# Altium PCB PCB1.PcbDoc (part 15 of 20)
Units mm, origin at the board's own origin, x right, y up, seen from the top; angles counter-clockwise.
Board outline 294.51 x 138.18 mm, 12 copper layers (Top Layer 1 _Signal, L2_GND, L3_Signals, L4_GND, L5_POWER, L6_Signals, L7_GND, L8_Signals, L9_GND, L10_POWER, L11_GND, Bottom Layer_Signals), stack 1.788 mm thick; 1254 components, 836 nets, 5699 pads, 2073 vias.
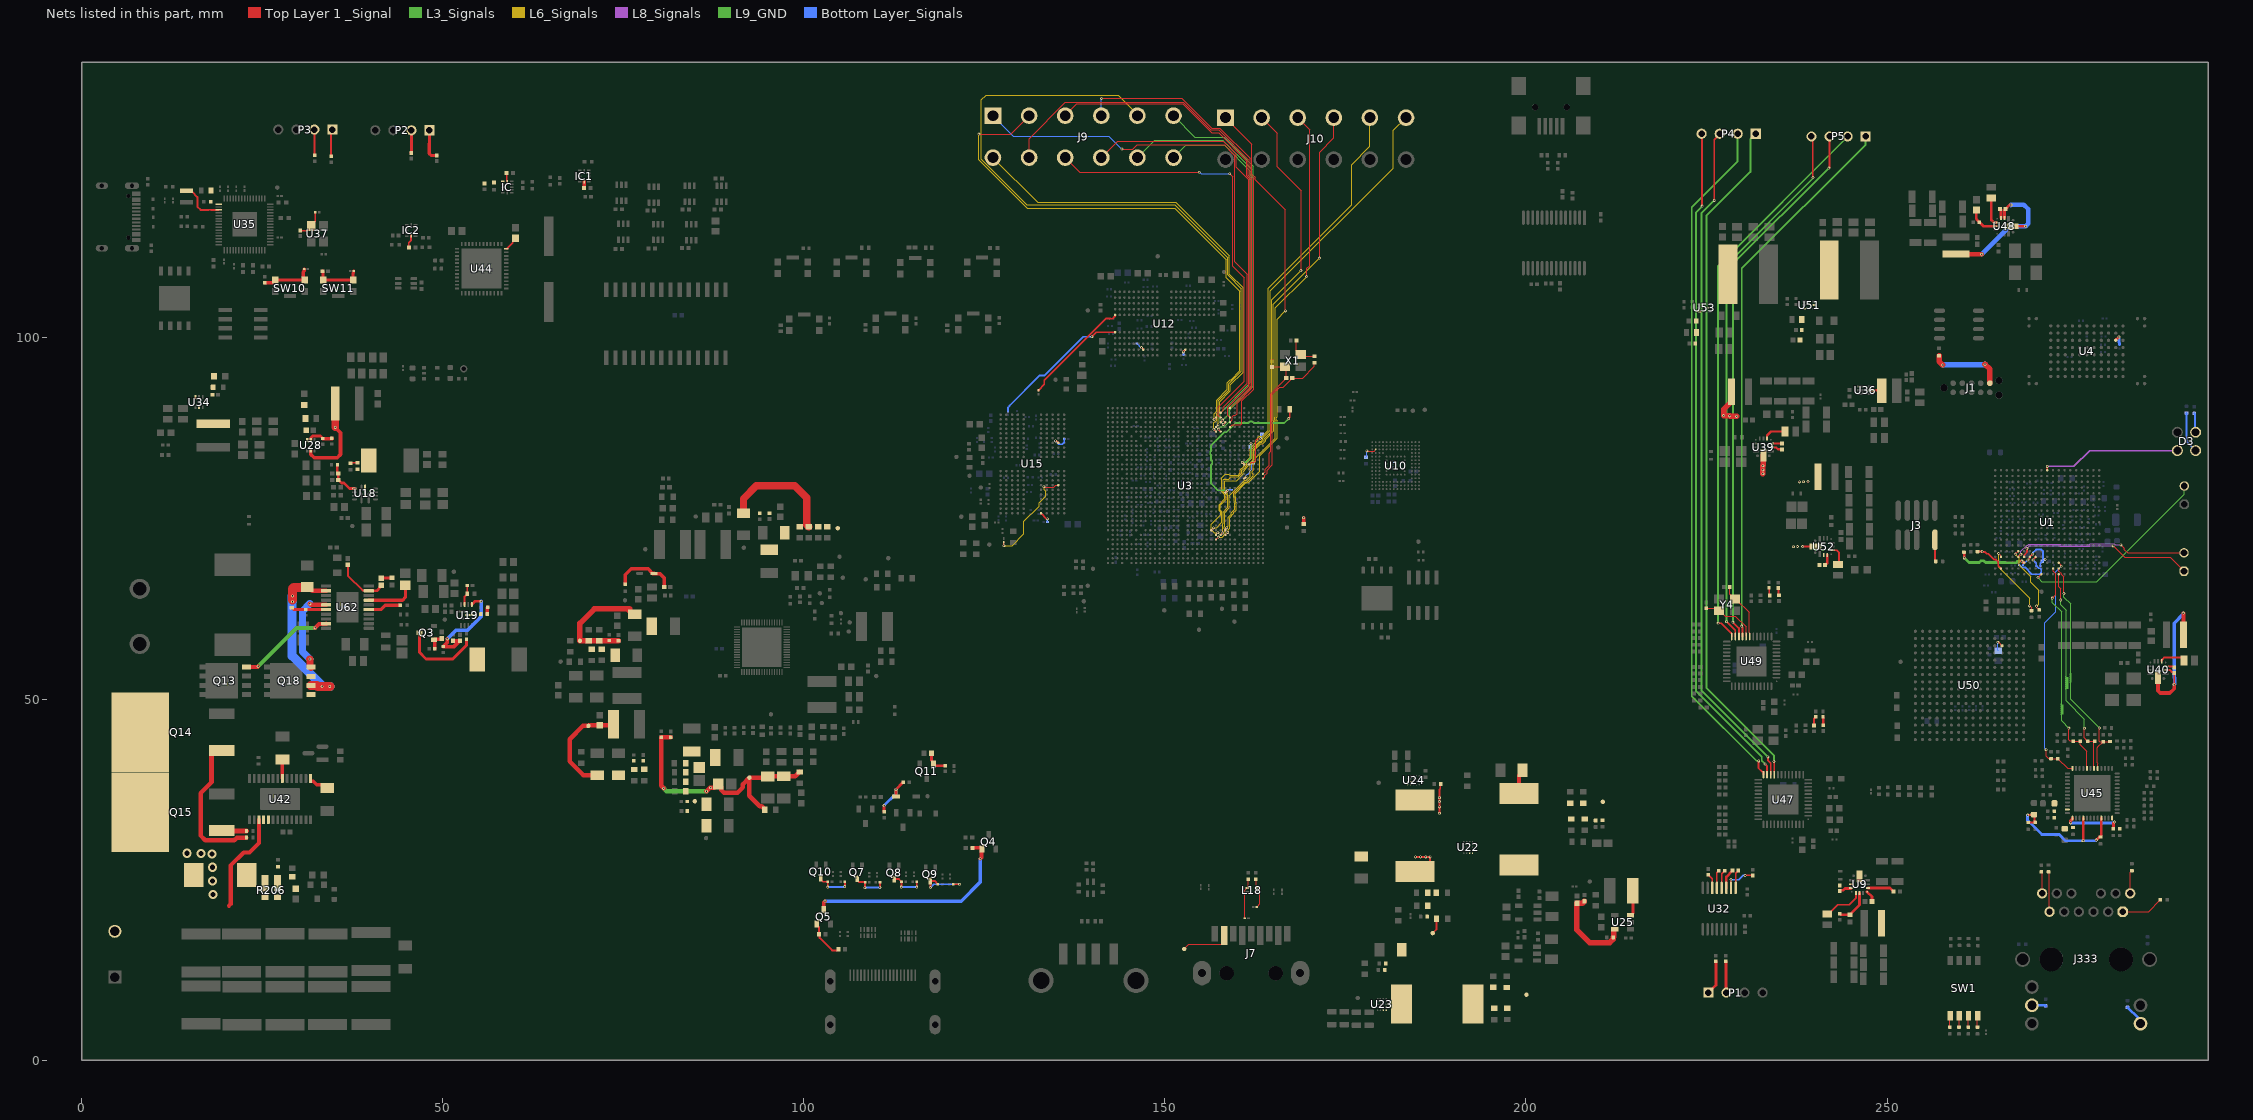
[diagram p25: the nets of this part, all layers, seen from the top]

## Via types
v1: diameter 0.4, hole 0.2, Top Layer 1 _Signal to Bottom Layer_Signals, 2009 vias
v2: diameter 0.508, hole 0.254, Top Layer 1 _Signal to Bottom Layer_Signals, 36 vias
v3: diameter 0.5, hole 0.2, Top Layer 1 _Signal to Bottom Layer_Signals, 12 vias
v4: diameter 1.27, hole 0.711, Top Layer 1 _Signal to Bottom Layer_Signals, 6 vias
v5: diameter 0.3, hole 0.2, Top Layer 1 _Signal to Bottom Layer_Signals, 5 vias
v6: diameter 0.254, hole 0.2, Top Layer 1 _Signal to Bottom Layer_Signals, 3 vias
v7: diameter 0.305, hole 0.2, Top Layer 1 _Signal to Bottom Layer_Signals, 1 vias
v8: diameter 0.254, hole 0.152, Top Layer 1 _Signal to Bottom Layer_Signals, 1 vias

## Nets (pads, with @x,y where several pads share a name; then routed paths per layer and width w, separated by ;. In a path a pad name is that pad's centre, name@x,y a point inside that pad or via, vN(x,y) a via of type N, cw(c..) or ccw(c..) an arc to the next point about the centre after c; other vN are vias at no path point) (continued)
MODE1: R383.1 R384.2 U1.J18 U45.32 | length 33.7
  Top Layer 1 _Signal w0.132: v1(272.878,63.972) 273.374,64.468 273.374,67.332 272.989,67.717 272.989,68.072 U1.J18@272.981,68.08 ; v1(275.173,45.975) 275.173,44.368 275.33,44.211 275.718,44.211 R384.2@275.781,44.148 275.788,44.141 R384.2@275.857,44.141 ; R384.2@275.857,44.14 R383.1@276.769,44.14 ; R383.1@276.769,44.14 276.769,43.64 277.674,42.735 U45.32@277.674,40.403
  L3_Signals w0.113: v1(272.878,63.972) 272.878,63.36 274.163,62.076 274.163,49.461 274.163,49.35 274.137,49.35 274.137,49.212 274.42,49.212 274.42,49.074 274.137,49.074 274.137,48.936 274.42,48.936 274.42,48.798 274.137,48.798 274.137,48.66 274.42,48.66 274.42,48.522 274.137,48.522 274.137,48.384 274.42,48.384 274.42,48.247 274.137,48.247 274.137,48.109 274.42,48.109 274.42,47.971 274.137,47.971 274.137,47.833 274.163,47.833 274.163,47.776 274.163,46.986 v1(275.173,45.975)
MODE2: R381.1 R382.2 U1.H19 U45.30 | length 33.3
  Top Layer 1 _Signal w0.132: U1.H19@273.781,67.28 273.781,65.555 274.052,65.285 v1(274.052,63.707) ; v1(277.324,45.953) 277.313,45.941 277.313,44.625 277.618,44.32 277.618,44.31 277.789,44.14 R381.1@277.799,44.14 R382.2@278.752,44.14 278.654,44.043 278.654,40.423 U45.30@278.674,40.403
  L3_Signals w0.113: v1(274.052,63.707) 274.052,63.041 274.798,62.295 274.798,53.327 274.798,53.163 274.772,53.163 274.772,53.025 275.079,53.025 275.079,52.887 274.772,52.887 274.772,52.749 275.079,52.749 275.079,52.611 274.772,52.611 274.772,52.473 275.079,52.473 275.079,52.335 274.772,52.335 274.772,52.198 275.079,52.198 275.079,52.06 274.772,52.06 274.772,51.922 275.079,51.922 275.079,51.784 274.772,51.784 274.772,51.646 275.079,51.646 275.079,51.508 274.772,51.508 274.772,51.37 274.798,51.37 274.798,51.314 274.798,49.736 277.324,47.21 v1(277.324,45.953)
MODE3: R376.1 R377.2 U1.H18 U45.29 | length 33.4
  Top Layer 1 _Signal w0.132: U1.H18@273.781,68.08 273.789,68.072 273.789,67.717 274.114,67.392 274.114,67.302 274.49,66.926 v1(274.49,64.589) ; U45.29@279.174,40.403 279.203,40.431 279.203,40.746 279.206,40.75 279.206,41.07 279.093,41.184 279.093,43.23 279.206,43.343 279.206,43.375 R376.1@279.926,44.094 ; v1(279.396,45.987) 279.396,44.172 279.473,44.094 R376.1@279.926,44.094 ; R377.2@280.866,44.118 280.854,44.106 279.954,44.106 R376.1@279.942,44.094 R376.1@279.926,44.094
  L3_Signals w0.113: v1(274.49,64.589) 274.49,64.086 275.414,63.162 275.414,53.702 275.414,53.602 275.542,53.602 275.542,53.464 275.388,53.464 275.388,53.327 275.542,53.327 275.542,53.189 275.388,53.189 275.388,53.051 275.542,53.051 275.542,52.913 275.388,52.913 275.388,52.775 275.542,52.775 275.542,52.637 275.388,52.637 275.388,52.499 275.542,52.499 275.542,52.361 275.388,52.361 275.388,52.223 275.414,52.223 275.414,52.167 275.414,49.969 v1(279.396,45.987)
MODE4: R374.1 R375.2 U1.H17 U45.36 | length 32.3
  Top Layer 1 _Signal w0.132: v1(272.03,42.969) 272.03,42.102 272.338,41.795 272.659,41.795 R374.1@272.712,41.742 273.398,41.742 273.406,41.75 273.647,41.75 R375.2@273.65,41.748 273.666,41.748 275.011,40.403 U45.36@275.674,40.403 ; U1.H17@273.781,68.88 274.065,68.596 274.065,68.438 v1(274.116,68.387)
  Bottom Layer_Signals w0.132: v1(272.03,42.969) 272.03,42.987 271.837,43.181 271.837,60.536 273.363,62.062 273.363,67.633 v1(274.116,68.387)
MP_FB: R84.1 R88.2 U19.11 | length 2.8
  Top Layer 1 _Signal w0.254: U19.11@53.038,63.083 53.038,64.187 53.398,64.547 R84.1@53.398,64.597 53.39,64.605 53.39,65.72 R88.2@53.383,65.728
nDETECT: J3.9 R8.1 | length 3
  Top Layer 1 _Signal w0.254: J3.9@256.631,72.048 256.631,69.188 256.749,69.07 R8.1@256.749,69.053
NetC10_2: C10.2 U4.E4 | length 1.7
  Top Layer 1 _Signal w0.381: U4.E4@281.672,99.669 281.672,99.687 v1(282.115,100.131)
  Bottom Layer_Signals w0.381: v1(282.115,100.131) 282.119,100.127 282.119,99.36 282.191,99.288 C10.2@282.191,99.091
NetC19_2: C19.2 R144.1 R145.1 U34.6
NetC31_2: C31.2 R23.1 U3.R34 X1.3 | length 18
  Top Layer 1 _Signal w0.161: U3.R34@163.579,81.178 163.904,81.502 163.904,81.802 164.471,82.369 164.471,84.054 164.627,84.209 ; 164.634,84.24 164.634,92.276 166.574,94.217 166.574,94.242 166.769,94.436 R23.1@166.794,94.436 166.794,95.841 X1.3@166.622,96.013 164.869,96.013 C31.2@164.827,95.971
NetC33_1: C33.1 R26.1 X1.1 | length 4.2
  Top Layer 1 _Signal w0.161: C33.1@168.218,99.647 168.218,98.232 168.738,97.713 X1.1@168.822,97.713 169.056,97.479 R26.1@170.71,97.479
NetC35_1: C35.1 J5.1 R253.1 U3.W26 | length 23.9
  Top Layer 1 _Signal w0.254: U3.W26@158.379,78.578 158.379,78.596 158.664,78.881 158.664,78.886 v1(158.678,78.9) ; v1(167.154,88.832) 167.154,88.872 167.285,89.002 R253.1@167.285,90.097
  Top Layer 1 _Signal w0.508: v1(169.211,75.094) 169.211,74.276 169.232,74.255 J5.1@169.237,74.255
  L3_Signals w0.254: v1(158.678,78.9) 157.349,78.9 156.41,79.84 156.41,82.408 156.558,82.556 156.558,82.896 156.41,83.045 156.41,83.789 156.286,83.913 156.286,84.253 156.41,84.377 156.41,85.129 158.226,86.946 158.531,86.946 159.802,88.217 161.581,88.217 161.77,88.406 162.11,88.406 162.299,88.217 166.539,88.217 v1(167.154,88.832)
  Bottom Layer_Signals w0.254: v1(158.678,78.9) 158.718,78.9 158.799,78.981 C35.1@159.271,78.981
NetC41_1: C41.1 C42.1 C43.2 C44.2 C45.1 L1.2 R28.2 R247.1 R248.1 TP10.1 | length 35.8
  Top Layer 1 _Signal w0.635: v1(80.6,37.619) 80.239,37.98 R28.2@80.239,44.715 81.554,44.715 C45.1@81.576,44.693 ; v1(86.532,37.232) 87.017,37.717 v1(87.108,37.717) 87.618,37.717 87.692,37.791 87.717,37.791 88.149,38.224 C43.2@88.149,38.249 88.582,37.816 88.582,37.406 88.954,37.034 90.828,37.034 91.577,37.784 91.577,38.212 TP10.1@92.468,39.103 ; C41.1@94.595,34.65 94.595,34.725 94.177,35.143 93.918,35.143 92.468,36.593 TP10.1@92.468,39.103 ; C42.1@99.453,39.899 99.378,39.899 99.321,39.842 99.321,39.767 98.844,39.29 R248.1@97.246,39.29 97.236,39.28 95.02,39.28 R247.1@95.01,39.269 94.844,39.103 TP10.1@92.468,39.103
  L3_Signals w0.635: v1(80.6,37.619) 80.986,37.232 v1(86.532,37.232)
NetC47_1: C47.1 U40.14 | length 1.1
  Top Layer 1 _Signal w0.254: U40.14@288.691,54.524 289.629,54.524 289.762,54.391 C47.1@289.762,54.372
NetC47_2: C47.2 L23.1 U40.10 U40.13 | length 21.3
  Top Layer 1 _Signal w0.254: U40.13@288.691,54.024 288.693,54.022 289.127,54.022 289.404,53.745 289.629,53.745 289.762,53.612 C47.2@289.762,53.592 v1(289.762,52.002)
  Top Layer 1 _Signal w0.508: U40.10@287.528,52.912 287.528,51.129 287.826,50.832 289.16,50.832 289.762,51.434 v1(289.762,52.002) ; v1(291.034,61.897) 291.044,61.886 L23.1@291.044,58.913
  Bottom Layer_Signals w0.508: v1(289.762,52.002) 289.82,52.06 289.82,52.933 289.762,52.99 289.762,55.108 289.76,55.11 289.76,60.503 291.034,61.777 v1(291.034,61.897)
NetC48_1: C48.1 U40.2 | length 3.6
  Top Layer 1 _Signal w0.254: U40.2@288.029,55.237 288.029,55.395 288.193,55.559 288.193,55.562 288.366,55.735 290.75,55.735 291.098,55.387 C48.1@291.098,55.342
NetC51_1: C51.1 C52.1 C53.1 C54.1 L2.2 R29.1 R148.1 R149.1 TP13.1 | length 14.6
  Top Layer 1 _Signal w0.635: R148.1@71.419,39.452 69.492,39.452 67.589,41.355 67.589,44.449 69.423,46.284 TP13.1@70.184,46.284 70.245,46.344 C52.1@71.744,46.344 73.508,46.344 L2.2@73.663,46.5
NetC61_1: C61.1 C62.1 C65.1 C66.1 C67.1 L5.2 R34.2 R286.1 R287.1 TP17.1 | length 16.6
  Top Layer 1 _Signal w0.762: C62.1@74.344,58.065 TP17.1@69.012,58.064 69.012,60.485 70.992,62.465 75.868,62.465 75.868,62.215 76.348,61.735 R287.1@76.598,61.735
NetC76_1: C76.1 C157.1 C158.1 C159.1 C160.1 L11.2 R36.2 R288.1 R289.1 TP25.1
NetC109_1: C109.1 C110.1 U1.M16 | length 6.6
  Top Layer 1 _Signal w0.254: v1(270.236,69.252) 270.236,69.315 270.581,69.66 U1.M16@270.581,69.68
  Bottom Layer_Signals w0.203: C109.1@268.283,68.567 268.629,68.221 269.13,68.221 270.068,67.283 271.129,67.283 271.365,67.519 271.365,67.97 271.246,68.089 271.007,68.089 C110.1@270.668,68.428
  Bottom Layer_Signals w0.254: v1(270.236,69.252) 270.668,68.82 270.668,68.428 C110.1@270.681,68.415
NetC109_2: C109.2 C110.2 R101.1 U1.N16 | length 6.7
  Top Layer 1 _Signal w0.254: v1(269.502,69.247) 269.521,69.247 269.766,69.492 269.766,69.665 U1.N16@269.781,69.68 v1(270.179,70.078)
  Bottom Layer_Signals w0.254: C109.2@268.823,68.567 v1(269.502,69.247) ; v1(270.179,70.078) 270.207,70.106 270.207,70.26 270.637,70.69 271.377,70.69 271.618,70.449 271.618,69.193 R101.1@271.522,69.096 ; C110.2@271.221,68.415 271.221,68.425 271.219,68.428 271.219,68.82 271.368,68.969 271.411,68.969 271.522,69.08 R101.1@271.522,69.096 ; v1(271.9,69.33) 271.86,69.33 271.754,69.223 271.632,69.223 271.522,69.113 R101.1@271.522,69.096
NetC162_1: C162.1 C163.1 C164.1 C165.1 C166.1 L12.2 R38.2 R290.1 R291.1 TP31.1 | length 16.4
  Top Layer 1 _Signal w1.016: R290.1@91.647,75.713 91.647,77.748 93.42,79.521 98.756,79.521 100.413,77.864 100.413,74.146 C165.1@100.706,73.854
NetC179_2: C179.2 D2.1 R39.2 | length 8.8
  Top Layer 1 _Signal w0.508: C179.2@75.286,65.919 75.286,67.222 76.105,68.042 78.461,68.042 78.759,67.744 78.759,67.708 79.076,67.392 D2.1@79.267,67.392 79.324,67.334 80.108,67.334 80.68,66.762 R39.2@80.68,65.534
NetC186_1: C186.1 U9.14 | length 1.8
  Top Layer 1 _Signal w0.381: C186.1@243.46,23.423 243.46,23.443 243.529,23.512 243.906,23.512 244.167,23.773 244.96,23.773 U9.14@245.026,23.838
NetC186_2: C186.2 L15.1 U9.10 U9.13
NetC192_1: C192.1 U62.5 | length 4.6
  Top Layer 1 _Signal w0.457: U62.5@39.768,62.386 41.436,62.386 42.04,62.989 C192.1@44.128,62.989
NetC193_1: C193.1 C218.1 U62.9 | length 7.4
  Top Layer 1 _Signal w0.254: C193.1@36.878,68.588 36.878,67.073 38.903,65.048 39.705,65.048 U62.9@39.768,64.986
  Top Layer 1 _Signal w0.381: U62.9@39.768,64.986 40.89,64.986 41.33,65.426 41.33,65.574 C218.1@41.499,65.743
NetC195_1: C195.1 U39.14 | length 1.4
  Top Layer 1 _Signal w0.3: U39.14@234.039,85.371 234.046,85.365 235.452,85.365 C195.1@235.458,85.358
NetC195_2: C195.2 L8.1 U39.10 U39.13 | length 9.8
  Top Layer 1 _Signal w0.3: U39.13@234.039,84.871 234.064,84.847 234.614,84.847 234.882,84.578 C195.2@235.458,84.578
  Top Layer 1 _Signal w0.762: L8.1@228.452,92.543 228.452,91.183 227.36,90.09 v1(227.36,89.246) 228.077,89.246 228.111,89.213 v1(228.193,89.213) 228.271,89.134 v1(229.175,89.134) ; v1(232.82,81.189) v1(232.82,81.719) 232.808,81.731 v1(232.808,82.304) 232.858,82.353 232.858,83.74 U39.10@232.877,83.759
NetC205_2: C205.2 U62.7 | length 6.9
  Top Layer 1 _Signal w0.457: U62.7@39.768,63.686 44.446,63.686 44.844,64.084 C205.2@44.844,65.75
NetC206_1: C206.1 R136.1 R138.2 U28.6
NetC216_2: C216.2 U10.C2 | length 2.3
  Top Layer 1 _Signal w0.089: v1(177.979,84.358) 178.001,84.336 178.97,84.336 U10.C2@179.204,84.57
  Bottom Layer_Signals w0.089: C216.2@177.836,83.488 177.979,83.63 v1(177.979,84.358)
NetC218_2: C218.2 R300.1 | length 1.5
  Top Layer 1 _Signal w0.381: C218.2@41.499,66.703 41.545,66.749 42.941,66.749 R300.1@42.987,66.795
NetC225_1: C225.1 D9.2 U62.16 | length 4.9
  Top Layer 1 _Signal w0.457: D9.2@29.084,62.637 29.134,62.637 29.375,62.396 32.32,62.396 32.33,62.386 U62.16@33.868,62.386
NetC313_1: C313.1 C386.1 C387.1 FB25.2 U45.1 U45.12 | length 7.9
  Top Layer 1 _Signal w0.4: v1(275.415,32.859) 275.415,33.154 275.674,33.413 U45.1@275.674,33.503 ; C387.1@281.334,32.053 281.334,32.794 v1(281.513,32.973)
  Bottom Layer_Signals w0.4: v1(275.415,32.859) 281.399,32.859 v1(281.513,32.973)
NetC369_1: C369.1 J333.12 | length 3
  Top Layer 1 _Signal w0.111: C369.1@271.365,26.055 271.476,25.945 J333.12@271.476,23.08
NetC370_1: C370.1 J333.6 | length 5.6
  Top Layer 1 _Signal w0.111: C370.1@272.362,26.071 272.492,25.941 272.492,20.549 J333.6@272.501,20.54
NetC371_1: C371.1 J333.1 | length 5.9
  Top Layer 1 _Signal w0.111: J333.1@282.651,20.54 286.212,20.54 287.842,22.171 C371.1@287.842,22.187
NetC372_1: C372.1 C373.1 FB24.1 U45.47
NetC374_1: C374.1 J333.7 | length 3.3
  Top Layer 1 _Signal w0.111: J333.7@283.676,23.08 283.676,26.001 283.906,26.231 C374.1@283.91,26.231
NetC389_1: C389.1 C390.1 C391.1 FB26.1 U45.4 U45.9 | length 21
  Top Layer 1 _Signal w0.254: v1(269.485,33.913) 269.512,33.941 270.397,33.941 FB26.1@270.434,33.905 ; C389.1@269.536,32.903 269.54,32.907 270.514,32.907 C390.1@270.518,32.911 270.434,32.996 FB26.1@270.434,33.905 ; FB26.1@270.349,33.989 FB26.1@270.434,33.905
  Top Layer 1 _Signal w0.381: v1(277.146,30.367) 277.174,30.396 U45.4@277.174,33.503 ; v1(278.987,30.47) 278.992,30.47 279.396,30.873 279.405,30.873 279.674,31.143 U45.9@279.674,33.503
  Bottom Layer_Signals w0.381: v1(269.485,33.913) 269.461,33.89 269.461,33.222 271.431,31.252 273.844,31.252 274.728,30.367 v1(277.146,30.367) 278.88,30.367 278.982,30.47 v1(278.987,30.47)
NetC436_1: C436.1 L16.1 U18.7
NetC436_2: C436.2 R78.2 | length 1
  Top Layer 1 _Signal w0.2: R78.2@37.244,82.667 37.273,82.696 38.147,82.696 C436.2@38.176,82.725
NetC439_1: C439.1 R79.1 R80.1 U18.9 | length 4.9
  Top Layer 1 _Signal w0.381: C439.1@35.41,82.432 35.41,81.357 35.525,81.242 R80.1@35.55,81.242 35.553,81.24 35.553,80.325 R79.1@35.555,80.322 35.58,80.322 35.989,79.914 36.318,79.914 37.094,79.137 U18.9@37.806,79.137
NetC445_1: C445.1 L17.1 U19.7
NetC445_2: C445.2 R82.2 | length 1
  Top Layer 1 _Signal w0.457: C445.2@56.189,61.746 56.189,62.634 56.237,62.683 R82.2@56.237,62.708
NetC448_1: C448.1 R83.1 R85.1 U19.9 | length 14.6
  Top Layer 1 _Signal w0.381: U19.9@54.038,63.083 54.038,63.177 54.104,63.242 54.198,63.242 54.488,63.532 v1(55.326,63.532)
  Top Layer 1 _Signal w0.508: v1(50.654,58.334) 50.654,57.844 C448.1@50.068,57.258 51.58,57.258 52.344,58.021 52.369,58.021 52.39,58.042 R85.1@52.39,58.067 52.385,58.072 51.439,58.072 R83.1@51.435,58.076
  Bottom Layer_Signals w0.508: v1(50.654,58.334) 51.836,59.516 53.446,59.516 55.354,61.424 55.354,63.505 v1(55.326,63.532)
NetC482_2: C482.2 Q11.1 R113.2 | length 3.4
  Top Layer 1 _Signal w0.381: C482.2@117.687,42.489 117.687,41.479 117.976,41.19 Q11.1@117.976,41.015 117.976,40.887 118.11,40.753 R113.2@119.593,40.753
NetC494_1: C494.1 C495.1 C496.1 C497.1 C499.2 L19.2 R120.2 R307.1 TP72.1 | length 3.4
  Top Layer 1 _Signal w0.508: L19.2@199.038,36.926 199.038,39.408 199.525,39.895 R307.1@199.525,40.145
NetC502_1: C502.1 C503.1 C504.1 C505.1 C507.2 L20.2 R121.2 R308.1 TP74.1
NetC511_1: C511.1 C512.1 C513.1 C514.1 C516.2 L21.2 R124.2 R309.1 TP75.1 | length 11.7
  Top Layer 1 _Signal w0.254: L21.2@184.635,26.115 185.401,26.115 186.724,27.438 v1(186.724,28.136) v1(186.13,28.136) 185.409,28.136 v1(185.401,28.128) 184.71,28.128 v1(184.703,28.136) ; TP75.1@187.09,17.58 187.615,18.106 C512.1@187.615,19.598 ; v1(188.012,34.186) v1(188.012,35.062) v1(188.012,35.792) v1(188.012,36.33) 188.012,37.445 188.139,37.572 188.139,38.171 R124.2@188.197,38.228
NetC517_1: C517.1 R125.2 R129.2 U25.5 | length 12.3
  Top Layer 1 _Signal w0.762: R125.2@208.107,22.002 207.816,21.711 C517.1@207.049,21.711 207.049,18.026 208.806,16.269 211.596,16.269 212.09,16.763 R129.2@212.09,17.009 212.177,17.096 212.177,18.056 212.258,18.137 U25.5@212.296,18.137
NetC526_1: C526.1 U9.2 | length 5.6
  Top Layer 1 _Signal w0.254: C526.1@241.724,20.238 241.924,20.238 243.197,21.512 244.795,21.512 245.688,22.406 U9.2@245.688,23.126
NetC527_1: C527.1 U48.14 | length 1.3
  Top Layer 1 _Signal w0.381: C527.1@265.637,117.851 265.657,117.851 265.769,117.739 U48.14@265.769,116.627
NetC527_2: C527.2 L24.1 U48.10 U48.13 | length 20.5
  Top Layer 1 _Signal w0.381: U48.13@266.269,116.627 266.269,117.723 266.397,117.851 C527.2@266.417,117.851 266.437,117.851 266.985,118.4 267.147,118.4 v1(267.151,118.403) ; U48.10@267.381,115.465 v1(269.187,115.465)
  Top Layer 1 _Signal w0.635: L24.1@259.539,111.594 v1(263.104,111.594)
  Bottom Layer_Signals w0.635: v1(263.104,111.594) 266.974,115.465 v1(269.187,115.465) 269.527,115.804 269.527,117.853 268.939,118.441 267.189,118.441 v1(267.151,118.403)
NetC537_1: C537.1 U48.2 | length 3.8
  Top Layer 1 _Signal w0.381: C537.1@264.444,119.359 264.444,116.327 264.74,116.03 264.991,116.03 U48.2@265.056,115.965
NetC542_1: C542.1 R188.1 U35.46
NetC546_1: C546.1 U32.1 | length 2.6
  Top Layer 1 _Signal w0.205: U32.1@229.043,23.842 229.043,25.877 C546.1@229.41,26.244
NetC546_2: C546.2 U32.3 | length 2.8
  Top Layer 1 _Signal w0.381: U32.3@227.743,23.842 227.743,25.377 C546.2@228.61,26.244
NetC548_1: C548.1 U32.2 | length 4.8
  Top Layer 1 _Signal w0.205: U32.2@228.393,23.842 v1(228.393,24.988) ; v1(230.354,25.565) 230.356,25.563 230.92,25.563 ; C548.1@231.401,25.563 C548.1@231.189,25.563 ; 230.92,25.563 C548.1@231.189,25.563 ; 230.92,25.563 C548.1@231.189,25.563
  Bottom Layer_Signals w0.205: v1(228.393,24.988) 229.497,24.988 230.093,25.583 230.41,25.583 v1@230.411,25.584 ; v1@230.413,25.584 v1@230.411,25.584 ; v1@230.441,25.614 v1@230.411,25.584
NetC549_1: C549.1 U32.4 | length 2.6
  Top Layer 1 _Signal w0.205: U32.4@227.093,23.842 227.093,25.802 C549.1@227.514,26.223
NetC549_2: C549.2 U32.5 | length 2.5
  Top Layer 1 _Signal w0.205: U32.5@226.443,23.842 226.443,25.952 C549.2@226.714,26.223
NetC550_1: C550.1 U32.6 | length 2
  Top Layer 1 _Signal w0.205: C550.1@225.238,25.651 225.793,25.097 U32.6@225.793,23.842
NetC559_2: C559.2 R197.1 SW10.3 SW10.4 | length 7.4
  Top Layer 1 _Signal w0.457: R197.1@25.356,107.659 26.501,107.659 26.807,107.964 SW10.4@26.807,108.014 30.685,108.014 SW10.3@30.907,108.014 30.685,108.235 30.685,108.549 30.681,108.553 30.681,109.136 30.815,109.27 C559.2@30.815,109.547
NetC560_1: C560.1 R200.1 U37.3 | length 3.9
  Top Layer 1 _Signal w0.203: R200.1@30.27,114.874 31.245,114.874 31.797,115.426 U37.3@31.797,115.526 31.797,115.626 32.33,116.159 C560.1@32.33,117.388
NetC564_2: C564.2 R204.1 SW11.3 SW11.4 | length 6.7
  Top Layer 1 _Signal w0.381: R204.1@33.389,109.251 33.395,109.251 33.441,109.206 33.441,108.071 SW11.4@33.493,108.019 SW11.3@37.593,108.019 37.593,108.955 37.702,109.064 C564.2@37.702,109.251
NetC586_1: C586.1 D13.1 R206.1 R206.3 R208.2 R209.2 U42.4 U42.5
NetC588_2: C588.2 U42.15 | length 3.1
  Top Layer 1 _Signal w0.457: U42.15@31.704,38.996 31.704,38.653 31.733,38.625 32.076,38.625 32.574,38.126 33.563,38.126 C588.2@34.01,37.68
NetC589_2: C589.2 U42.21 | length 2.6
  Top Layer 1 _Signal w0.457: U42.21@27.805,38.996 27.805,41.615 C589.2@27.815,41.625
NetC591_1: C591.1 U44.48 | length 2
  Top Layer 1 _Signal w0.254: U44.48@58.789,112.359 58.96,112.359 58.962,112.361 58.962,112.416 59.701,113.155 59.701,113.403 C591.1@60.074,113.776
NetC593_1: C593.1 R228.2 | length 1.2
  Top Layer 1 _Signal w0.3: R228.2@241.136,47.525 241.159,47.503 241.159,46.385 C593.1@241.181,46.363
NetC594_1: C594.1 R229.2 | length 1.3
  Top Layer 1 _Signal w0.3: C594.1@239.897,46.35 239.897,47.259 240.138,47.5 R229.2@240.138,47.525
NetC601_1: C601.1 U39.2 | length 3
  Top Layer 1 _Signal w0.3: U39.2@233.377,86.222 233.377,86.497 233.926,87.047 C601.1@235.856,87.047
NetC602_1: C602.1 U52.14 | length 1.5
  Top Layer 1 _Signal w0.381: C602.1@241.424,68.551 241.444,68.551 241.513,68.62 241.513,68.64 241.738,68.865 241.738,69.937 U52.14@241.733,69.942
NetC602_2: C602.2 L26.1 U52.10 U52.13 | length 1.8
  Top Layer 1 _Signal w0.3: v1(238.307,71.105) U52.10@240.12,71.105
  other v1: 237.044,71.091 237.595,71.118 237.87,80.072 238.421,80.092 239.053,80.099
NetC606_1: C606.1 U49.20 Y4.3 | length 7.9
  Top Layer 1 _Signal w0.161: C606.1@224.97,62.564 226.435,62.564 Y4.3@226.755,62.244 226.855,62.244 227.619,61.479 229.012,61.479 230.476,60.016 230.476,58.67 U49.20@230.491,58.655
NetC607_1: C607.1 R249.2 | length 1
  Top Layer 1 _Signal w0.254: R249.2@234.952,65.373 234.992,65.334 234.992,64.407 C607.1@235.032,64.368
NetC608_1: C608.1 R251.2 | length 1.1
  Top Layer 1 _Signal w0.254: R251.2@233.653,65.399 233.7,65.352 233.7,64.396 C608.1@233.748,64.348
NetC618_1: C618.1 U49.19 Y4.1 | length 8.1
  Top Layer 1 _Signal w0.161: C618.1@228.209,65.524 228.209,64.49 228.855,63.844 229.055,63.844 230.896,62.003 230.896,59.18 230.991,59.085 U49.19@230.991,58.655
NetC619_2: C619.2 U50.D3 | length 2
  Top Layer 1 _Signal w0.152: v1(265.343,57.861) 265.438,57.861 U50.D3@265.919,57.379
  Bottom Layer_Signals w0.152: v1(265.343,57.861) 265.343,56.729 C619.2@265.403,56.669
NetC626_1: C626.1 U52.2 | length 2.9
  Top Layer 1 _Signal w0.254: U52.2@242.604,70.604 U52.2@242.446,70.604 243.039,70.604 243.363,70.281 243.363,68.784 C626.1@243.216,68.638
NetC643_1: C643.1 C644.1 IC.1
NetC670_2: C670.2 R254.1 R266.2 U51.6
NetC678_2: C678.2 R268.1 R270.2 U53.6
NetD3_2: D3.2 R21.2 | length 2.7
  Bottom Layer_Signals w0.254: R21.2@292.549,89.542 292.644,89.447 292.644,87.037 D3.2@292.739,86.941
NetD3_3: D3.3 U1.K1 | length 19.5
  Top Layer 1 _Signal w0.203: U1.K1@272.181,81.68 v1(272.181,82.204)
  L8_Signals w0.203: v1(272.181,82.204) 275.858,82.204 278.055,84.401 D3.3@290.199,84.401
NetD3_4: D3.4 R22.2 | length 5.7
  Bottom Layer_Signals w0.254: R22.2@291.468,89.589 291.468,85.672 D3.4@292.739,84.401
NetD7_2: D7.2 R106.2 R108.2 | length 6.2
  Top Layer 1 _Signal w0.381: R106.2@111.121,34.379 v1(111.121,35.232) ; D7.2@112.774,36.514 v1(112.774,37.489) 113.772,38.486 R108.2@113.779,38.486
  Bottom Layer_Signals w0.381: v1(111.121,35.232) 112.771,36.882 112.771,37.485 v1(112.774,37.489)
NetD13_2: D13.2 J8.2
  other v4: 18.19,22.935 18.145,24.8 18.123,26.71 18.055,28.53 16.55,28.619 14.573,28.642
NetIC1_12: IC1.12 R283.2 | length 0.9
  Top Layer 1 _Signal w0.508: R283.2@69.567,120.771 69.588,120.792 69.588,121.376 69.602,121.39 IC1.12@69.602,121.668
NetIC2_12: IC2.12 R273.2 | length 1.8
  Top Layer 1 _Signal w0.254: R273.2@45.303,112.527 45.303,113.191 45.624,113.512 45.624,114.124 IC2.12@45.642,114.143
NetIC_12: IC.12 R277.2 | length 1.2
  Top Layer 1 _Signal w0.254: R277.2@58.868,122.854 58.868,121.81 58.94,121.738 IC.12@58.94,121.642
NetJ1_6: J1.6 R2.1 | length 10.3
  Top Layer 1 _Signal w0.762: R2.1@257.201,97.551 257.201,96.754 v1(257.701,96.254) ; v1(263.565,96.345) 264.236,95.675 J1.6@264.236,93.732
  Bottom Layer_Signals w0.762: v1(257.701,96.254) 263.474,96.254 v1(263.565,96.345)
NetJ2_1: J2.1 U1.P16 | length 24.7
  Top Layer 1 _Signal w0.089: v1(281.302,71.196) 281.345,71.196 282.895,69.646 289.183,69.646 J2.1@291.128,67.7
  Top Layer 1 _Signal w0.254: U1.P16@268.981,69.701 268.996,69.715 268.996,69.927 269.382,70.314 269.382,70.807 v1(269.372,70.818)
  L8_Signals w0.089: v1(269.372,70.818) 269.784,71.231 273.891,71.231 273.95,71.171 278.057,71.171 278.089,71.203 281.295,71.203 v1(281.302,71.196)
NetJ2_2: J2.2 U1.R16 | length 24.6
  Top Layer 1 _Signal w0.089: v1(282.384,71.345) 282.875,70.853 282.875,70.673 283.308,70.24 J2.2@291.128,70.24
  Top Layer 1 _Signal w0.132: U1.R16@268.181,69.68 268.525,70.024 v1(268.525,70.039)
  L8_Signals w0.089: v1(268.525,70.039) 268.543,70.057 268.543,70.454 269.413,71.324 269.515,71.324 269.595,71.403 273.962,71.403 274.022,71.344 277.985,71.344 278.166,71.524 281.438,71.524 281.617,71.345 v1(282.384,71.345)
NetJ7_1: J7.1 TP68.1 | length 6.8
  Top Layer 1 _Signal w0.131: TP68.1@152.676,15.388 153.316,16.027 157.807,16.027 158.191,16.412 J7.1@158.191,17.262
NetJ9_1: J9.1 U3.B25 | length 74.2
  Top Layer 1 _Signal w0.132: v1(144.055,126.159) 145.547,126.159 146.168,126.78 158.198,126.78 158.933,126.045 158.933,126.003 159.695,125.242 159.695,110.519 161.384,108.83 161.384,93.721 158.07,90.406 158.07,89.968 U3.B25@157.729,89.628
  Bottom Layer_Signals w0.132: J9.1@126.2,130.773 129.023,127.95 142.264,127.95 v1(144.055,126.159)
NetJ9_2: J9.2 U3.C24 | length 76.3
  Top Layer 1 _Signal w0.132: v1(124.248,128.226) 128.652,128.226 J9.2@131.2,130.773 ; v1@156.799,88.72 v1(156.81,88.732) 156.822,88.732 157.068,88.978 U3.C24@157.079,88.978
  L6_Signals w0.132: v1(124.248,128.226) 124.248,124.642 130.956,117.934 151.353,117.934 158.493,110.794 158.493,108.64 158.523,108.61 158.523,108.32 160.389,106.454 160.389,95.452 159.159,94.222 159.056,94.222 158.648,93.814 158.648,92.867 157.155,91.375 157.155,89.831 156.81,89.486 v1(156.81,88.732)
NetJ9_3: J9.3 U3.A27 | length 64.7
  Top Layer 1 _Signal w0.132: J9.3@136.2,130.773 137.83,132.404 152.483,132.404 156.468,128.419 157.435,128.419 161.364,124.49 161.364,122.44 161.84,121.964 161.84,93.088 U3.A27@159.029,90.278
NetJ9_4: J9.4 U3.E27 | length 65.8
  Top Layer 1 _Signal w0.132: v1(141.233,133.169) 152.356,133.169 156.459,129.066 157.587,129.066 161.795,124.858 161.795,122.618 162.277,122.137 162.277,92.915 160.639,91.278 160.639,88.1 160.526,87.988 159.339,87.988 U3.E27@159.029,87.678
  Bottom Layer_Signals w0.132: J9.4@141.2,130.773 141.216,130.79 141.216,133.152 v1(141.233,133.169)
NetJ9_5: J9.5 U3.F24 | length 97.8
  Top Layer 1 _Signal w0.132: v1(156.779,87.351) 156.78,87.327 U3.F24@157.079,87.028
  L6_Signals w0.132: J9.5@146.2,130.773 146.2,130.967 143.567,133.599 125.239,133.599 124.598,132.958 124.598,124.737 130.893,118.442 151.391,118.442 158.709,111.124 158.709,108.729 160.605,106.833 160.605,95.363 158.864,93.622 158.864,92.778 157.371,91.285 157.371,89.742 157.166,89.536 157.166,88.661 157.16,88.655 157.16,88.587 156.955,88.382 156.887,88.382 156.779,88.274 v1(156.779,87.351)
NetJ9_6: J9.6 U3.F25 | length 53.2
  Top Layer 1 _Signal w0.132: v1@157.386,87.371 v1(157.393,87.364) U3.F25@157.729,87.028
  L3_Signals w0.132: J9.6@151.2,130.773 154.173,127.8 158.227,127.8 162.271,123.756 162.271,93.316 159.258,90.303 159.232,90.303 159.027,90.098 159.027,90.072 159.009,90.054 159.009,88.473 158.224,87.688 157.717,87.688 v1(157.393,87.364)
NetJ9_7: J9.7 U3.E24 | length 64.4
  Top Layer 1 _Signal w0.132: U3.E24@157.079,87.678 157.089,87.678 157.372,87.961 v1(157.381,87.961) v1@157.381,87.97
  L6_Signals w0.132: J9.7@126.2,124.973 132.407,118.766 151.528,118.766 158.925,111.369 158.925,108.819 160.821,106.923 160.821,95.274 159.079,93.532 159.079,92.689 157.587,91.196 157.587,89.652 157.381,89.447 v1(157.381,87.961)
NetJ9_8: J9.8 U3.D27 | length 76.3
  Top Layer 1 _Signal w0.132: J9.8@131.2,124.973 131.2,127.611 136.208,132.619 152.572,132.619 156.362,128.83 157.431,128.83 161.58,124.681 161.58,122.529 162.061,122.047 162.061,93.005 160.02,90.963 160.02,89.53 159.777,89.288 159.551,89.288 159.339,89.076 159.339,88.638 U3.D27@159.029,88.328
NetJ9_9: J9.9 U3.C25 | length 59.9
  Top Layer 1 _Signal w0.132: J9.9@136.2,124.973 138.226,122.947 v1(154.763,122.947) ; U3.C25@157.729,88.978 157.42,89.288 157.42,90.406 161.007,93.994 161.007,108.317 159.403,109.921 159.403,122.313 v1(158.984,122.733)
  Bottom Layer_Signals w0.132: v1(154.763,122.947) 154.835,122.947 155.05,122.733 v1(158.984,122.733)
NetJ9_10: J9.10 U3.C27 | length 58.9
  Top Layer 1 _Signal w0.132: J9.10@141.2,124.973 143.476,127.25 158.093,127.25 159.023,126.32 159.023,126.293 159.91,125.405 159.91,123.603 161.121,122.392 161.121,122.377 161.624,121.875 161.624,93.311 158.718,90.404 158.718,89.29 U3.C27@159.029,88.978
NetJ9_11: J9.11 U3.D25 | length 55.3
  Top Layer 1 _Signal w0.132: U3.D25@157.729,88.328 v1(158.014,88.613)
  L3_Signals w0.132: J9.11@146.2,124.973 148.598,127.371 158.028,127.371 162.055,123.344 162.055,93.405 159.168,90.518 159.143,90.518 158.812,90.187 158.812,90.162 158.794,90.144 158.794,89.392 v1(158.014,88.613)
NetJ9_12: J9.12 U3.D26 | length 50.2
  Top Layer 1 _Signal w0.132: v1(158.079,88.037) 158.084,88.037 158.375,88.328 U3.D26@158.379,88.328
  L3_Signals w0.132: J9.12@151.2,124.973 152.88,126.654 158.283,126.654 161.84,123.097 161.84,93.764 157.664,89.589 157.664,88.453 v1(158.079,88.037)
NetJ10_1: J10.1 U3.AH26 | length 65.1
  Top Layer 1 _Signal w0.132: J10.1@158.395,130.504 162.055,126.843 162.055,122.663 162.492,122.226 162.492,121.936 166.697,117.732 v1(166.697,103.741)
  Top Layer 1 _Signal w0.165: U3.AH26@158.379,72.728 158.687,73.036 158.687,73.059 v1(158.706,73.077)
  L6_Signals w0.106: v1(158.706,73.077) 158.762,73.134 158.762,73.431 158.97,73.639 158.97,74.321 158.97,75.092 159.57,75.692 159.57,75.866 159.87,76.166 159.87,76.746 159.882,76.757 159.882,77.194 159.802,77.273 159.802,77.914 159.723,77.993 159.723,78.43 161.214,79.921 161.526,79.921 163.135,81.53 163.135,83.684 165.542,86.09 165.542,88.559 165.419,88.681 165.419,88.961 165.542,89.083 165.542,102.586 v1(166.697,103.741)
NetJ10_2: J10.2 U3.AH25 | length 66.1
  Top Layer 1 _Signal w0.132: J10.2@163.395,130.504 165.575,128.323 165.575,123.683 168.89,120.369 168.89,109.372 v1(168.841,109.323)
  Top Layer 1 _Signal w0.161: U3.AH25@157.729,72.728 157.741,72.728 158.003,72.99 v1(158.015,72.99)
  L6_Signals w0.106: v1(158.015,72.99) 158.015,74.287 158.099,74.371 158.099,75.894 158.362,76.157 158.362,76.235 158.708,76.58 158.708,78.262 158.659,78.31 158.659,78.404 158.668,78.413 158.668,78.501 158.605,78.563 158.539,78.563 158.291,78.811 158.291,80.188 158.354,80.25 159.927,80.25 160.849,81.172 160.849,81.502 161.303,81.955 161.303,82.049 161.531,82.277 161.531,82.418 162.212,83.1 162.212,84.505 163.233,85.526 163.45,85.526 163.759,85.835 163.759,86.052 164.813,87.106 164.813,105.295 v1(168.841,109.323)
NetJ10_3: J10.3 U3.AG26 | length 63.1
  Top Layer 1 _Signal w0.132: J10.3@168.395,130.504 170.041,128.857 170.041,110.015 169.671,109.644 169.671,108.523 v1(169.634,108.486)
  Top Layer 1 _Signal w0.165: U3.AG26@158.379,73.378 158.379,73.42 158.515,73.555 158.515,73.66 v1(158.56,73.705)
  L6_Signals w0.106: v1(158.56,73.705) 158.56,73.773 158.78,73.994 158.78,75.171 159.208,75.599 159.208,75.773 159.68,76.245 159.68,76.824 159.691,76.836 159.691,77.115 159.607,77.2 159.607,77.841 159.533,77.914 159.533,78.509 161.135,80.111 161.404,80.111 162.232,80.939 162.232,81.158 162.112,81.278 162.112,81.557 162.232,81.678 162.232,82.581 162.593,82.942 162.593,83.41 165.294,86.111 165.294,88.538 165.229,88.603 165.229,89.039 165.294,89.104 165.294,104.146 v1(169.634,108.486)
NetJ10_4: J10.4 U3.AJ24 | length 66
  Top Layer 1 _Signal w0.132: U3.AJ24@157.079,72.078 157.404,72.403 v1(157.404,72.426) v1@157.399,72.426 ; v1(171.406,111.063) 171.444,111.1 171.444,125.74 173.395,127.691 J10.4@173.395,130.504
  L6_Signals w0.106: v1(157.404,72.426) 157.927,72.426 158.352,72.85 158.352,73.13 158.302,73.179 158.302,73.333 158.335,73.366 158.335,73.454 158.223,73.566 158.223,73.845 158.321,73.943 158.321,75.497 158.289,75.528 158.289,75.816 158.552,76.079 158.552,76.156 158.898,76.501 158.898,78.143 161.056,80.301 161.264,80.301 161.801,80.838 161.801,82.42 162.402,83.021 162.402,84.426 163.312,85.335 163.529,85.335 163.949,85.756 163.949,85.973 165.095,87.119 165.095,88.467 165.039,88.524 165.039,104.696 v1(171.406,111.063)
NetJ10_5: J10.5 U3.AH24 | length 69.7
  Top Layer 1 _Signal w0.161: U3.AH24@157.079,72.728 157.079,72.741 157.347,73.009 v1(157.347,73.022)
  L6_Signals w0.106: v1(157.347,73.022) 156.815,73.022 156.415,73.422 156.415,74.22 157.719,75.523 157.719,75.858 157.498,76.079 157.498,76.926 158.279,77.707 158.279,78.285 157.865,78.699 157.865,79.857 157.905,79.897 157.905,80.334 157.865,80.374 157.865,80.627 158.362,81.125 158.84,81.125 158.966,80.998 160.133,80.998 160.469,81.334 160.469,81.754 160.652,81.937 160.725,81.937 160.922,82.134 160.922,82.207 161.15,82.435 161.15,82.803 161.832,83.484 161.832,84.739 162.895,85.802 162.895,86.193 163.092,86.39 163.483,86.39 164.286,87.193 164.286,106.853 175.856,118.424 175.856,123.985 178.395,126.524 J10.5@178.395,130.504
NetJ10_6: J10.6 U3.AG23 | length 70.2
  Top Layer 1 _Signal w0.132: U3.AG23@156.429,73.378 v1(156.758,73.707)
  L6_Signals w0.106: v1(156.758,73.707) 157.166,73.707 157.909,74.45 157.909,75.937 157.688,76.157 157.688,76.847 158.469,77.628 158.469,78.364 158.101,78.732 158.101,80.389 158.163,80.451 158.827,80.451 159.025,80.648 159.025,80.706 159.087,80.769 160.173,80.769 160.659,81.255 160.659,81.675 160.731,81.746 160.804,81.746 161.113,82.055 161.113,82.128 161.341,82.356 161.341,82.724 162.022,83.405 162.022,84.616 163.122,85.716 163.154,85.716 163.371,85.716 163.569,85.913 163.569,86.131 163.569,86.163 164.623,87.217 164.623,106.525 181.615,123.517 181.615,128.724 J10.6@183.395,130.504
NetJ34_2: J34.2 U1.L19 | length 27.3
  Top Layer 1 _Signal w0.132: v1(270.906,66.805) U1.L19@271.381,67.28
  L3_Signals w0.161: v1(270.906,66.805) 271.441,66.27 271.662,66.27 271.723,66.208 272.025,66.208 272.087,66.27 279.056,66.27 291.166,78.38 J34.2@291.166,79.496
NetJ333_14: J333.14 R398.1 | length 3
  Bottom Layer_Signals w0.381: R398.1@283.303,7.296 283.319,7.296 284.804,5.812 284.804,5.342 J333.14@285.096,5.05
NetJ333_16: J333.16 R401.1 | length 1.9
  Bottom Layer_Signals w0.381: J333.16@270.056,7.59 271.855,7.59 271.946,7.5 R401.1@271.962,7.5
NetL6_1: L6.1 U28.2 | length 12.4
  Top Layer 1 _Signal w0.5: U28.2@31.737,84.371 31.737,83.867 32.211,83.393 35.38,83.393 35.854,83.867 35.854,86.885 v1(35.129,87.61)
  Top Layer 1 _Signal w1.016: v1(35.129,87.61) 35.129,90.889 L6.1@35.143,90.902
NetL9_1: L9.1 U36.2 | length 1.5
  Top Layer 1 _Signal w0.381: U36.2@247.739,92.753 249.214,92.753 L9.1@249.262,92.706
NetL14_1: L14.1 U34.2
NetL18_1: L18.1 R92.1 R93.2 | length 5.7
  Top Layer 1 _Signal w0.131: R92.1@161.07,19.636 161.042,19.665 161.042,23.518 161.341,23.817 L18.1@161.441,23.817 161.462,23.817 161.547,23.901 R93.2@161.547,25.066
NetL18_4: L18.4 R94.2 R95.1 | length 4.4
  Top Layer 1 _Signal w0.131: R94.2@162.586,25.061 162.631,25.015 162.631,23.852 L18.4@162.666,23.817 162.751,23.733 163.023,23.733 163.161,23.595 163.161,21.648 162.849,21.336 162.849,21.29 162.783,21.225 R95.1@162.738,21.225
NetL19_1: L19.1 U22.D3 U22.D4 U22.E3 U22.E4
NetL20_1: L20.1 U23.D3 U23.D4 U23.E3 U23.E4
NetL21_1: L21.1 U24.D3 U24.D4 U24.E3 U24.E4
NetL22_1: L22.1 U25.3 | length 3.7
  Top Layer 1 _Signal w0.381: U25.3@214.496,20.037 214.696,20.037 214.806,20.146 214.806,20.346 214.809,20.349 L22.1@214.809,23.452
NetL25_2: L25.2 U35.48 | length 6.4
  Top Layer 1 _Signal w0.254: L25.2@14.491,120.387 14.664,120.214 15.324,120.214 16.039,119.499 16.039,118.176 16.487,117.728 17.566,117.728 17.577,117.738 17.917,117.738 17.928,117.728 U35.48@18.994,117.728
NetL27_1: L27.1 U51.2
NetL28_1: L28.1 U53.2
NetP1_1: P1.1 R169.2 | length 4.8
  Top Layer 1 _Signal w0.381: P1.1@225.27,9.345 226.302,10.376 R169.2@226.302,13.671
NetP1_2: P1.2 R168.2 | length 4.4
  Top Layer 1 _Signal w0.381: R168.2@227.666,13.671 227.668,13.671 227.712,13.628 227.712,9.403 P1.2@227.77,9.345
NetP2_1: P2.1 R191.2 | length 4.4
  Top Layer 1 _Signal w0.457: P2.1@48.17,128.751 48.17,126.921 48.139,126.889 48.139,125.53 48.406,125.262 R191.2@49.205,125.262
NetP2_2: P2.2 R193.2 | length 3.2
  Top Layer 1 _Signal w0.457: R193.2@45.634,125.607 45.634,125.629 45.67,125.665 P2.2@45.67,128.751
NetP3_1: P3.1 R201.2 | length 3.8
  Top Layer 1 _Signal w0.254: R201.2@34.544,125.153 34.544,128.664 P3.1@34.732,128.853
NetP3_2: P3.2 R202.2 | length 3.6
  Top Layer 1 _Signal w0.254: P3.2@32.232,128.853 32.257,128.828 32.257,125.308 R202.2@32.282,125.284
NetP4_1: P4.1 U47.21 | length 95.1
  Top Layer 1 _Signal w0.254: v1(234.335,41.371) 234.363,41.343 234.363,41.165 234.388,41.141 U47.21@234.388,39.937
  L3_Signals w0.254: P4.1@231.822,128.272 231.087,127.537 231.087,122.991 224.994,116.897 224.994,51.556 234.335,42.214 v1(234.335,41.371)
NetP4_2: P4.2 U47.24 | length 95.8
  Top Layer 1 _Signal w0.254: v1(232.233,41.435) 232.233,41.395 232.184,41.346 232.184,40.45 232.698,39.937 232.88,39.937 232.887,39.929 U47.24@232.887,39.535
  L3_Signals w0.254: P4.2@229.322,128.272 229.278,128.228 229.278,124.407 223.149,118.278 222.961,118.089 222.961,50.406 231.925,41.441 232.227,41.441 v1(232.233,41.435)
NetP4_3: P4.3 U47.22 | length 93.8
  Top Layer 1 _Signal w0.254: v1(226.074,119.038) 226.074,127.435 226.822,128.183 P4.3@226.822,128.272 ; v1(233.511,41.976) 233.538,41.948 233.538,41.449 233.887,41.1 U47.22@233.887,39.535
  L3_Signals w0.254: v1(226.074,119.038) 224.287,117.25 224.287,51.2 v1(233.511,41.976)
NetP4_4: P4.4 U47.23 | length 93.2
  Top Layer 1 _Signal w0.254: P4.4@224.322,128.272 224.375,128.218 224.375,118.272 v1(224.403,118.244) ; v1(233.109,40.999) 233.109,40.959 233.387,40.681 U47.23@233.387,39.535
  L3_Signals w0.254: v1(224.403,118.244) 223.57,117.411 223.57,51.074 232.644,42 232.644,41.464 v1(233.109,40.999)
NetP5_1: P5.1 U49.21 | length 76.4
  Top Layer 1 _Signal w0.254: v1(229.888,60.089) 229.888,60.049 229.991,59.946 U49.21@229.991,58.655
  L3_Signals w0.254: v1(229.888,60.089) 229.888,109.628 247.04,126.78 P5.1@247.04,127.892
NetP5_2: P5.2 U49.24 | length 77.7
  Top Layer 1 _Signal w0.254: v1(226.598,60.503) 227.037,60.503 228.491,59.05 U49.24@228.491,58.655
  L3_Signals w0.254: v1(226.598,60.503) 226.598,109.951 P5.2@244.54,127.892
NetP5_3: P5.3 U49.22 | length 75.1
  Top Layer 1 _Signal w0.254: v1(228.661,60.655) 229.491,59.826 U49.22@229.491,58.655 ; v1(241.937,123.518) 241.937,123.558 242.04,123.661 P5.3@242.04,127.892
  L3_Signals w0.254: v1(228.661,60.655) 228.661,110.243 v1(241.937,123.518)
NetP5_4: P5.4 U49.23 | length 74.8
  Top Layer 1 _Signal w0.254: v1(227.782,60.702) 228.991,59.494 U49.23@228.991,58.655 ; P5.4@239.54,127.892 239.722,127.711 239.722,122.226 v1(239.749,122.198)
  L3_Signals w0.254: v1(227.782,60.702) 227.782,110.153 239.749,122.12 v1(239.749,122.198)
NetQ3_1: Q3.1 R89.1 R90.2 | length 2.5
  Top Layer 1 _Signal w0.457: R89.1@48.9,56.972 48.9,58.135 48.828,58.207 Q3.1@48.792,58.207 48.863,58.278 49.811,58.278 R90.2@49.887,58.354
NetQ3_3: Q3.3 R87.1 | length 11.3
  Top Layer 1 _Signal w0.381: Q3.3@46.772,59.157 46.725,59.11 46.772,59.064 46.772,56.472 47.717,55.527 51.393,55.527 53.314,57.448 R87.1@53.314,58.261
NetQ4_1: Q4.1 Q5.3 R102.1 | length 30
  Top Layer 1 _Signal w0.508: Q5.3@102.752,20.843 102.752,21.821 v1(102.942,22.011) ; R102.1@123.339,29.383 124.603,29.383 124.674,29.312 Q4.1@124.674,29.214 124.603,29.143 124.603,28.049 v1(124.442,27.888)
  Bottom Layer_Signals w0.508: v1(102.942,22.011) 121.807,22.011 124.442,24.647 v1(124.442,27.888)
NetQ5_1: Q5.1 R103.1 R105.2 | length 5.5
  Top Layer 1 _Signal w0.26: Q5.1@101.802,18.843 101.802,18.71 101.885,18.626 102.094,18.417 R105.2@102.094,17.418 102.191,17.321 102.191,16.913 103.918,15.186 104.133,15.186 ; 104.134,15.186 104.638,15.186 R103.1@104.794,15.343
NetQ7_3: Q7.3 R109.1 R110.1 | length 5
  Top Layer 1 _Signal w0.254: Q7.3@107.408,25.104 107.408,24.886 107.653,24.641 R109.1@108.492,24.641 108.492,23.888 v1(108.473,23.868) ; v1(110.543,23.909) 110.548,23.914 110.548,24.649 R110.1@110.554,24.655
  Bottom Layer_Signals w0.254: v1(108.473,23.868) 108.493,23.889 110.522,23.889 v1(110.543,23.909)
NetQ8_3: Q8.3 R111.1 R112.1 | length 4.8
  Top Layer 1 _Signal w0.254: Q8.3@112.515,25.067 113.185,25.067 R111.1@113.532,24.72 113.514,24.703 113.514,23.976 v1(113.497,23.959) ; v1(115.647,23.959) 115.655,23.967 115.655,24.681 R112.1@115.663,24.689
  Bottom Layer_Signals w0.254: v1(113.497,23.959) v1(115.647,23.959)
NetQ9_3: Q9.3 R115.1 R116.1 | length 7.2
  Top Layer 1 _Signal w0.254: v1(117.524,23.883) 117.529,23.887 117.529,24.807 Q9.3@117.534,24.811 118.131,24.811 R115.1@118.563,24.38 ; R116.1@120.713,24.354 121.569,24.354 v1(121.573,24.35)
  Bottom Layer_Signals w0.254: v1(117.524,23.883) 117.992,24.35 v1(121.573,24.35)
NetQ10_3: Q10.3 R117.1 R118.1 | length 5.1
  Top Layer 1 _Signal w0.254: Q10.3@102.377,25.216 102.337,25.176 102.337,25.021 102.666,24.692 R117.1@103.308,24.692 103.315,24.685 v1(103.315,23.964) ; v1(105.679,24.029) 105.686,24.036 105.686,24.701 R118.1@105.694,24.708
  Bottom Layer_Signals w0.254: v1(103.315,23.964) 105.575,23.964 105.64,24.029 v1(105.679,24.029)
NetQ13_4: Q13.4 U62.19 | length 13.5
  Top Layer 1 _Signal w0.6: Q13.4@22.813,54.433 24.349,54.433 v1(24.43,54.513) ; v1(32.327,59.843) 32.879,60.395 33.827,60.395 U62.19@33.868,60.436
  L3_Signals w0.6: v1(24.43,54.513) 29.76,59.843 v1(32.327,59.843)
NetQ14_1: Q14.1 R205.1 | length 20.4
  Top Layer 1 _Signal w0.635: Q14.1@19.417,42.876 18.417,42.876 17.985,42.444 17.985,38.492 16.471,36.978 16.471,31.1 17.117,30.453 21.161,30.453 21.513,30.805 R205.1@22.826,30.805
NetQ14_2: Q14.2 Q15.2 R206.2 R206.4 U42.3 | length 14.1
  Top Layer 1 _Signal w0.6: 20.401,21.396 20.63,21.625 20.63,26.939 22.448,28.757 23.246,28.757 24.554,30.066 U42.3@24.554,33.296
NetQ15_1: Q15.1 R207.1 | length 3.4
  Top Layer 1 _Signal w0.635: Q15.1@19.417,31.777 19.474,31.72 R207.1@22.843,31.72
NetQ18_1: Q18.1 Q18.2 Q18.3 R299.2 U62.12 | length 25.5
  Top Layer 1 _Signal w0.6: R299.2@31.224,65.514 31.399,65.514 31.927,64.986 U62.12@33.868,64.986
  Top Layer 1 _Signal w1.27: 29.185,63.716 29.185,65.262 29.372,65.449 31.159,65.449 R299.2@31.224,65.514 R299.2@31.049,65.514 ; Q18.2@31.76,51.868 32.576,51.868 32.693,51.751 v1(33.314,51.751) v1(34.361,51.751)
  Bottom Layer_Signals w1.27: v1@29.153,64.29 29.153,55.972 v1@33.314,51.812 ; v1(29.201,63.462) v1(29.201,64.29) ; v1(33.314,51.751) v1(34.361,51.751)
NetQ18_4: Q18.4 U62.15 | length 12
  Top Layer 1 _Signal w0.6: v1(31.606,63.175) 31.745,63.036 U62.15@33.868,63.036
  Top Layer 1 _Signal w1.016: v1(31.606,55.544) 31.633,55.517 31.633,54.538 Q18.4@31.76,54.411
  Bottom Layer_Signals w1.016: v1(31.606,55.544) 30.599,56.551 30.599,62.168 v1(31.606,63.175)
NetR1_1: R1.1 U1.V18 | length 4.5
  Top Layer 1 _Signal w0.254: R1.1@262.522,70.411 v1(263.164,70.411) 263.21,70.365 263.524,70.365 263.785,70.104 264.025,70.104 264.825,69.304 265.089,69.304 265.405,68.988 265.405,68.476 265.781,68.101 U1.V18@265.781,68.08
NetR3_2: R3.2 U3.T30 | length 2.8
  Top Layer 1 _Signal w0.132: U3.T30@160.979,80.528 160.997,80.528 161.226,80.757 v1(161.243,80.757)
  Bottom Layer_Signals w0.132: v1(161.243,80.757) 161.284,80.798 161.284,81.015 161.422,81.153 161.472,81.153 161.75,81.431 161.75,81.518 162.028,81.796 162.028,82.523 162.198,82.693 R3.2@162.232,82.693
NetR4_2: R4.2 U1.R15 | length 9.9
  Top Layer 1 _Signal w0.132: v1(267.782,70.074) 267.782,70.081 U1.R15@268.181,70.48 ; v1(270.7,62.853) 270.752,62.802 270.752,62.649 271.069,62.332 R4.2@271.079,62.332
  L6_Signals w0.132: v1(267.782,70.074) 268.328,69.528 268.328,68.498 269.914,66.913 269.914,66.141 270.998,65.057 270.998,63.151 v1(270.7,62.853)
NetR6_2: R6.2 U1.V16 | length 10.4
  Top Layer 1 _Signal w0.132: v1(265.452,70.151) 265.743,69.86 265.743,69.718 U1.V16@265.781,69.68 ; v1(269.741,62.899) 270.005,62.636 R6.2@270.005,62.243
  L6_Signals w0.132: v1(265.452,70.151) 265.452,68.226 269.741,63.936 v1(269.741,62.899)
NetR7_1: R7.1 U1.P17 | length 9.9
  Top Layer 1 _Signal w0.381: R7.1@260.648,70.339 260.649,70.339 260.696,70.292 260.696,69.537 v1(260.7,69.533) ; v1@268.62,69.148 v1(268.678,69.09) 268.683,69.09 268.876,68.897 268.981,68.897 U1.P17@268.981,68.88
  L9_GND w0.381: v1(260.7,69.533) 261.346,68.887 262.752,68.887 263.004,69.138 263.397,69.138 263.648,68.887 266.421,68.887 266.454,68.853 267.869,68.853 268.102,69.087 268.674,69.087 v1(268.678,69.09)
NetR10_2: R10.2 SW1.8 | length 1.6
  Top Layer 1 _Signal w0.132: R10.2@262.526,4.57 262.526,6.127 SW1.8@262.551,6.153
NetR12_2: R12.2 SW1.7 | length 1.6
  Top Layer 1 _Signal w0.132: R12.2@261.256,4.57 261.256,6.127 SW1.7@261.281,6.153
NetR13_2: R13.2 SW1.6 | length 1.6
  Top Layer 1 _Signal w0.132: R13.2@259.973,4.57 259.973,6.114 SW1.6@260.011,6.153
NetR15_2: R15.2 SW1.5 | length 1.6
  Top Layer 1 _Signal w0.132: R15.2@258.703,4.57 258.703,6.114 SW1.5@258.741,6.153
NetR23_2: R23.2 R26.2 U3.T34 | length 20.1
  Top Layer 1 _Signal w0.161: U3.T34@163.579,80.528 163.579,80.571 163.812,80.804 163.812,80.952 164.149,81.289 164.149,81.7 164.717,82.268 164.717,82.289 164.898,82.471 164.898,92.168 165.935,93.205 166.388,93.205 167.619,94.436 R23.2@167.644,94.436 169.059,94.436 170.71,96.087 R26.2@170.71,96.579
NetR24_1: R24.1 U3.N31 | length 5.4
  Top Layer 1 _Signal w0.132: U3.N31@161.629,82.478 161.939,82.788 162.377,82.788 162.589,83 162.589,85.826 162.816,86.053 v1(163.232,86.053)
  Bottom Layer_Signals w0.132: v1(163.232,86.053) 163.437,86.259 R24.1@163.437,86.678
NetR25_1: R25.1 U3.N30 | length 4.5
  Top Layer 1 _Signal w0.203: v1(160.711,82.774) 160.711,82.767 160.979,82.499 U3.N30@160.979,82.478
  L3_Signals w0.203: v1(160.711,82.774) 161.25,82.774 161.863,83.387 161.863,85.335 v1(161.932,85.403)
  Bottom Layer_Signals w0.203: R25.1@161.799,84.868 161.831,84.837 161.841,84.837 161.894,84.889 161.894,85.365 v1(161.932,85.403)
NetR43_2: R43.2 R52.2 U9.3 | length 5
  Top Layer 1 _Signal w0.381: R52.2@243.456,20.258 243.458,20.258 243.583,20.134 R43.2@244.856,20.134 244.858,20.134 246.188,21.464 U9.3@246.188,23.126
NetR44_2: R44.2 U12.G2 | length 1.3
  Top Layer 1 _Signal w0.205: v1(146.764,98.671) 146.764,98.65 147.004,98.409 U12.G2@147.004,98.389
  Bottom Layer_Signals w0.127: R44.2@146.133,99.212 146.183,99.212 146.459,98.936 146.459,98.84 146.576,98.723 146.712,98.723 v1(146.764,98.671)
NetR45_2: R45.2 U12.T2 | length 0.8
  Top Layer 1 _Signal w0.203: v1(152.545,98.069) 152.545,98.074 152.854,98.384 U12.T2@152.854,98.389
  Bottom Layer_Signals w0.254: v1(152.545,98.069) 152.545,98.029 152.586,97.988 152.586,97.691 R45.2@152.588,97.689
NetR46_2: R46.2 U12.A5 | length 19.7
  Top Layer 1 _Signal w0.254: v1(139.884,100.168) 140.505,100.789 U12.A5@143.104,100.789
  Bottom Layer_Signals w0.254: R46.2@128.259,89.846 128.264,89.85 128.264,90.31 128.484,90.531 128.484,90.636 132.634,94.786 133.297,94.786 138.679,100.168 v1(139.884,100.168)
NetR47_2: R47.2 U12.A8 | length 15.4
  Top Layer 1 _Signal w0.254: R47.2@132.509,92.735 132.509,92.781 133.309,93.58 133.309,94.142 139.303,100.136 139.303,100.168 141.815,102.68 142.397,102.68 142.425,102.653 142.765,102.653 143.086,102.974 143.086,103.171 U12.A8@143.104,103.189
NetR48_2: R48.2 U15.G2 | length 14
  Top Layer 1 _Signal w0.132: R48.2@127.687,71.676 127.696,71.667 127.696,71.238 v1(127.706,71.229) ; v1(133.256,79.386) 133.279,79.386 133.442,79.222 133.516,79.296 134.585,79.296 134.877,79.589 135.218,79.589 U15.G2@135.25,79.621
  L6_Signals w0.132: v1(127.706,71.229) 128.845,71.229 130.468,72.852 130.468,74.614 132.578,76.724 132.578,77.166 133.52,78.109 133.52,78.76 133.292,78.988 133.292,79.35 v1(133.256,79.386)
NetR49_2: R49.2 U15.T2 | length 2.5
  Top Layer 1 _Signal w0.254: v1(134.855,85.75) 134.945,85.75 135.224,85.471 U15.T2@135.25,85.471
  Bottom Layer_Signals w0.254: v1(134.855,85.75) 135.321,85.285 135.82,85.285 136.061,85.525 136.061,85.991 136.063,85.993 R49.2@136.084,85.993
NetR50_2: R50.2 U9.5 | length 1.6
  Top Layer 1 _Signal w0.381: U9.5@247.243,23.306 247.917,22.631 R50.2@247.917,21.954
NetR51_2: R51.2 U15.A5 | length 1.6
  Top Layer 1 _Signal w0.203: U15.A5@132.85,75.721 133.595,74.976 133.704,74.976 v1(133.741,74.938)
  Bottom Layer_Signals w0.203: v1(133.741,74.938) 133.746,74.933 133.746,74.539 R51.2@133.751,74.534
NetR53_2: R53.2 U9.6 | length 3.7
  Top Layer 1 _Signal w0.381: U9.6@247.351,23.838 250.397,23.838 R53.2@250.88,23.356
NetR54_2: R54.2 R162.2 U48.3 | length 4.4
  Top Layer 1 _Signal w0.381: R54.2@262.362,117.72 262.362,116.49 262.468,116.384 262.468,116.332 R162.2@262.764,116.034 R162.2@262.764,116.034 262.764,116.032 263.331,115.465 U48.3@265.056,115.465
NetR55_1: R55.1 R137.2 U28.5 | length 3.6
  Top Layer 1 _Signal w0.4: U28.5@31.737,85.871 31.787,85.921 31.787,86.223 31.969,86.405 33.067,86.405 R137.2@33.409,86.063
  Top Layer 1 _Signal w0.5: R137.2@33.409,86.063 34.682,86.063 R55.1@34.635,86.11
